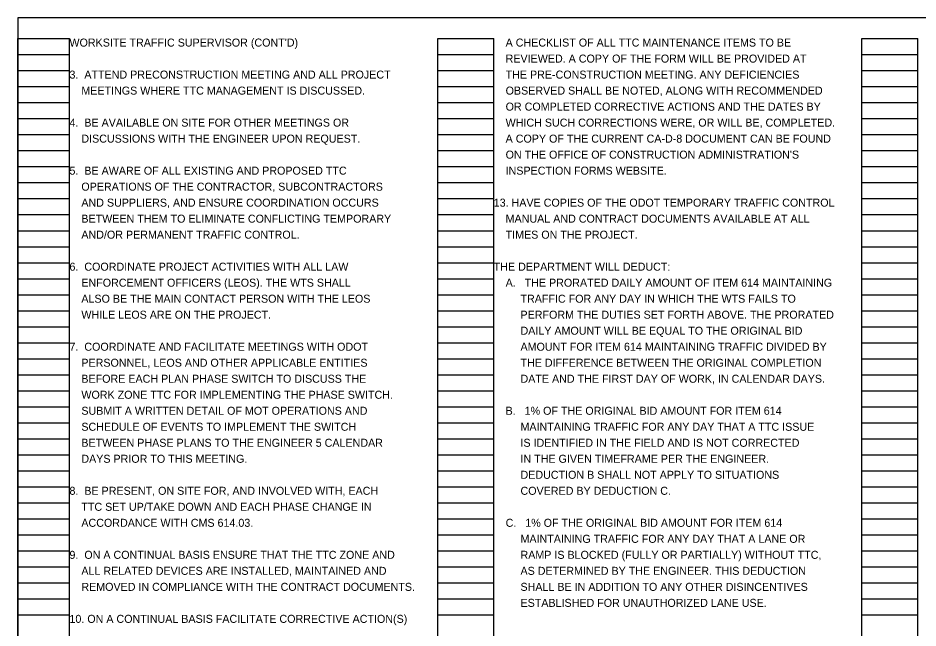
# Model space of a CAD drawing. Extents: x -34 to 2132911, y 0 to 658646.
# Drawn here: x 69.5 to 85.24, y 10.83 to 21.5 of the extents above; entities that cross this region are included whole.
import ezdxf

# ---------------------------------------------------------------- set-up
doc = ezdxf.new("R2010")
doc.units = 0
for name, color, linetype in [('SC_Scratch1', 7, 'Continuous'), ('SH_Data', 7, 'Continuous'), ('SH_Text', 7, 'Continuous')]:
    doc.layers.add(name, color=color, linetype=linetype)

msp = doc.modelspace()

# ---------------------------------------------------------------- linework, layer by layer
at = {"layer": 'SC_Scratch1'}
msp.add_lwpolyline([(69.5, 0.5), (100, 0.5), (100, 21.5), (69.5, 21.5)], close=True, dxfattribs=at)
at = {"layer": 'SH_Data'}
for p, q in [((69.5, 0.98), (69.5, 21.14)), ((69.5, 21.14), (70.4, 21.14)), ((70.4, 0.98), (70.4, 21.14)), ((76.84, 0.98), (76.84, 21.14)), ((76.84, 21.14), (77.82, 21.14)), ((77.82, 0.98), (77.82, 21.14)), ((84.26, 0.98), (84.26, 21.14)), ((84.26, 21.14), (85.24, 21.14)), ((85.24, 0.98), (85.24, 21.14)), ((69.5, 20.86), (70.4, 20.86)), ((76.84, 20.86), (77.82, 20.86)), ((84.26, 20.86), (85.24, 20.86)), ((69.5, 20.58), (70.4, 20.58)), ((76.84, 20.58), (77.82, 20.58)), ((84.26, 20.58), (85.24, 20.58)), ((69.5, 20.3), (70.4, 20.3)), ((76.84, 20.3), (77.82, 20.3)), ((84.26, 20.3), (85.24, 20.3)), ((69.5, 20.02), (70.4, 20.02)), ((76.84, 20.02), (77.82, 20.02)), ((84.26, 20.02), (85.24, 20.02)), ((69.5, 19.74), (70.4, 19.74)), ((76.84, 19.74), (77.82, 19.74)), ((84.26, 19.74), (85.24, 19.74)), ((69.5, 19.46), (70.4, 19.46)), ((76.84, 19.46), (77.82, 19.46)), ((84.26, 19.46), (85.24, 19.46)), ((69.5, 19.18), (70.4, 19.18)), ((76.84, 19.18), (77.82, 19.18)), ((84.26, 19.18), (85.24, 19.18)), ((69.5, 18.9), (70.4, 18.9)), ((76.84, 18.9), (77.82, 18.9)), ((84.26, 18.9), (85.24, 18.9)), ((69.5, 18.62), (70.4, 18.62)), ((76.84, 18.62), (77.82, 18.62)), ((84.26, 18.62), (85.24, 18.62)), ((69.5, 18.34), (70.4, 18.34)), ((76.84, 18.34), (77.82, 18.34)), ((84.26, 18.34), (85.24, 18.34)), ((69.5, 18.06), (70.4, 18.06)), ((76.84, 18.06), (77.82, 18.06)), ((84.26, 18.06), (85.24, 18.06)), ((69.5, 17.78), (70.4, 17.78)), ((76.84, 17.78), (77.82, 17.78)), ((84.26, 17.78), (85.24, 17.78)), ((69.5, 17.5), (70.4, 17.5)), ((76.84, 17.5), (77.82, 17.5)), ((84.26, 17.5), (85.24, 17.5)), ((69.5, 17.22), (70.4, 17.22)), ((76.84, 17.22), (77.82, 17.22)), ((84.26, 17.22), (85.24, 17.22)), ((69.5, 16.94), (70.4, 16.94)), ((76.84, 16.94), (77.82, 16.94)), ((84.26, 16.94), (85.24, 16.94)), ((69.5, 16.66), (70.4, 16.66)), ((76.84, 16.66), (77.82, 16.66)), ((84.26, 16.66), (85.24, 16.66)), ((69.5, 16.38), (70.4, 16.38)), ((76.84, 16.38), (77.82, 16.38)), ((84.26, 16.38), (85.24, 16.38)), ((69.5, 16.1), (70.4, 16.1)), ((76.84, 16.1), (77.82, 16.1)), ((84.26, 16.1), (85.24, 16.1)), ((69.5, 15.82), (70.4, 15.82)), ((76.84, 15.82), (77.82, 15.82)), ((84.26, 15.82), (85.24, 15.82)), ((69.5, 15.54), (70.4, 15.54)), ((76.84, 15.54), (77.82, 15.54)), ((84.26, 15.54), (85.24, 15.54)), ((69.5, 15.26), (70.4, 15.26)), ((76.84, 15.26), (77.82, 15.26)), ((84.26, 15.26), (85.24, 15.26)), ((69.5, 14.98), (70.4, 14.98)), ((76.84, 14.98), (77.82, 14.98)), ((84.26, 14.98), (85.24, 14.98)), ((69.5, 14.7), (70.4, 14.7)), ((76.84, 14.7), (77.82, 14.7)), ((84.26, 14.7), (85.24, 14.7)), ((69.5, 14.42), (70.4, 14.42)), ((76.84, 14.42), (77.82, 14.42)), ((84.26, 14.42), (85.24, 14.42)), ((69.5, 14.14), (70.4, 14.14)), ((76.84, 14.14), (77.82, 14.14)), ((84.26, 14.14), (85.24, 14.14)), ((69.5, 13.86), (70.4, 13.86)), ((76.84, 13.86), (77.82, 13.86)), ((84.26, 13.86), (85.24, 13.86)), ((69.5, 13.58), (70.4, 13.58)), ((76.84, 13.58), (77.82, 13.58)), ((84.26, 13.58), (85.24, 13.58)), ((69.5, 13.3), (70.4, 13.3)), ((76.84, 13.3), (77.82, 13.3)), ((84.26, 13.3), (85.24, 13.3)), ((69.5, 13.02), (70.4, 13.02)), ((76.84, 13.02), (77.82, 13.02)), ((84.26, 13.02), (85.24, 13.02)), ((69.5, 12.74), (70.4, 12.74)), ((76.84, 12.74), (77.82, 12.74)), ((84.26, 12.74), (85.24, 12.74)), ((69.5, 12.46), (70.4, 12.46)), ((76.84, 12.46), (77.82, 12.46)), ((84.26, 12.46), (85.24, 12.46)), ((69.5, 12.18), (70.4, 12.18)), ((76.84, 12.18), (77.82, 12.18)), ((84.26, 12.18), (85.24, 12.18)), ((69.5, 11.9), (70.4, 11.9)), ((76.84, 11.9), (77.82, 11.9)), ((84.26, 11.9), (85.24, 11.9)), ((69.5, 11.62), (70.4, 11.62)), ((76.84, 11.62), (77.82, 11.62)), ((84.26, 11.62), (85.24, 11.62)), ((69.5, 11.34), (70.4, 11.34)), ((76.84, 11.34), (77.82, 11.34)), ((84.26, 11.34), (85.24, 11.34)), ((69.5, 11.06), (70.4, 11.06)), ((76.84, 11.06), (77.82, 11.06)), ((84.26, 11.06), (85.24, 11.06))]:
    msp.add_line(p, q, dxfattribs=at)

# ---------------------------------------------------------------- texts
at = {"layer": 'SH_Text'}
for s, p in [("WORKSITE TRAFFIC SUPERVISOR (CONT'D)", (70.4, 21)), ('    A CHECKLIST OF ALL TTC MAINTENANCE ITEMS TO BE', (77.82, 21)), ('    REVIEWED. A COPY OF THE FORM WILL BE PROVIDED AT', (77.82, 20.72)), ('3.  ATTEND PRECONSTRUCTION MEETING AND ALL PROJECT', (70.4, 20.44)), ('    THE PRE-CONSTRUCTION MEETING. ANY DEFICIENCIES', (77.82, 20.44)), ('    MEETINGS WHERE TTC MANAGEMENT IS DISCUSSED.', (70.4, 20.16)), ('    OBSERVED SHALL BE NOTED, ALONG WITH RECOMMENDED', (77.82, 20.16)), ('    OR COMPLETED CORRECTIVE ACTIONS AND THE DATES BY', (77.82, 19.88)), ('4.  BE AVAILABLE ON SITE FOR OTHER MEETINGS OR', (70.4, 19.6)), ('    WHICH SUCH CORRECTIONS WERE, OR WILL BE, COMPLETED.', (77.82, 19.6)), ('    DISCUSSIONS WITH THE ENGINEER UPON REQUEST.', (70.4, 19.32)), ('    A COPY OF THE CURRENT CA-D-8 DOCUMENT CAN BE FOUND', (77.82, 19.32)), ("    ON THE OFFICE OF CONSTRUCTION ADMINISTRATION'S", (77.82, 19.04)), ('5.  BE AWARE OF ALL EXISTING AND PROPOSED TTC', (70.4, 18.76)), ('    INSPECTION FORMS WEBSITE.', (77.82, 18.76)), ('    OPERATIONS OF THE CONTRACTOR, SUBCONTRACTORS', (70.4, 18.48)), ('    AND SUPPLIERS, AND ENSURE COORDINATION OCCURS', (70.4, 18.2)), ('13. HAVE COPIES OF THE ODOT TEMPORARY TRAFFIC CONTROL', (77.82, 18.2)), ('    BETWEEN THEM TO ELIMINATE CONFLICTING TEMPORARY', (70.4, 17.92)), ('    MANUAL AND CONTRACT DOCUMENTS AVAILABLE AT ALL', (77.82, 17.92)), ('    AND/OR PERMANENT TRAFFIC CONTROL.', (70.4, 17.64)), ('    TIMES ON THE PROJECT.', (77.82, 17.64)), ('6.  COORDINATE PROJECT ACTIVITIES WITH ALL LAW', (70.4, 17.08)), ('THE DEPARTMENT WILL DEDUCT:', (77.82, 17.08)), ('    ENFORCEMENT OFFICERS (LEOS). THE WTS SHALL', (70.4, 16.8)), ('    A.   THE PRORATED DAILY AMOUNT OF ITEM 614 MAINTAINING', (77.82, 16.8)), ('    ALSO BE THE MAIN CONTACT PERSON WITH THE LEOS', (70.4, 16.52)), ('         TRAFFIC FOR ANY DAY IN WHICH THE WTS FAILS TO', (77.82, 16.52)), ('    WHILE LEOS ARE ON THE PROJECT.', (70.4, 16.24)), ('         PERFORM THE DUTIES SET FORTH ABOVE. THE PRORATED', (77.82, 16.24)), ('         DAILY AMOUNT WILL BE EQUAL TO THE ORIGINAL BID', (77.82, 15.96)), ('7.  COORDINATE AND FACILITATE MEETINGS WITH ODOT', (70.4, 15.68)), ('         AMOUNT FOR ITEM 614 MAINTAINING TRAFFIC DIVIDED BY', (77.82, 15.68)), ('    PERSONNEL, LEOS AND OTHER APPLICABLE ENTITIES', (70.4, 15.4)), ('         THE DIFFERENCE BETWEEN THE ORIGINAL COMPLETION', (77.82, 15.4)), ('    BEFORE EACH PLAN PHASE SWITCH TO DISCUSS THE', (70.4, 15.12)), ('         DATE AND THE FIRST DAY OF WORK, IN CALENDAR DAYS.', (77.82, 15.12)), ('    WORK ZONE TTC FOR IMPLEMENTING THE PHASE SWITCH.', (70.4, 14.84)), ('    SUBMIT A WRITTEN DETAIL OF MOT OPERATIONS AND', (70.4, 14.56)), ('    B.   1% OF THE ORIGINAL BID AMOUNT FOR ITEM 614', (77.82, 14.56)), ('    SCHEDULE OF EVENTS TO IMPLEMENT THE SWITCH', (70.4, 14.28)), ('         MAINTAINING TRAFFIC FOR ANY DAY THAT A TTC ISSUE', (77.82, 14.28)), ('    BETWEEN PHASE PLANS TO THE ENGINEER 5 CALENDAR', (70.4, 14)), ('         IS IDENTIFIED IN THE FIELD AND IS NOT CORRECTED', (77.82, 14)), ('    DAYS PRIOR TO THIS MEETING.', (70.4, 13.72)), ('         IN THE GIVEN TIMEFRAME PER THE ENGINEER.', (77.82, 13.72)), ('         DEDUCTION B SHALL NOT APPLY TO SITUATIONS', (77.82, 13.44)), ('8.  BE PRESENT, ON SITE FOR, AND INVOLVED WITH, EACH', (70.4, 13.16)), ('         COVERED BY DEDUCTION C.', (77.82, 13.16)), ('    TTC SET UP/TAKE DOWN AND EACH PHASE CHANGE IN', (70.4, 12.88)), ('    ACCORDANCE WITH CMS 614.03.', (70.4, 12.6)), ('    C.   1% OF THE ORIGINAL BID AMOUNT FOR ITEM 614', (77.82, 12.6)), ('         MAINTAINING TRAFFIC FOR ANY DAY THAT A LANE OR', (77.82, 12.32)), ('9.  ON A CONTINUAL BASIS ENSURE THAT THE TTC ZONE AND', (70.4, 12.04)), ('         RAMP IS BLOCKED (FULLY OR PARTIALLY) WITHOUT TTC,', (77.82, 12.04)), ('    ALL RELATED DEVICES ARE INSTALLED, MAINTAINED AND', (70.4, 11.76)), ('         AS DETERMINED BY THE ENGINEER. THIS DEDUCTION', (77.82, 11.76)), ('    REMOVED IN COMPLIANCE WITH THE CONTRACT DOCUMENTS.', (70.4, 11.48)), ('         SHALL BE IN ADDITION TO ANY OTHER DISINCENTIVES', (77.82, 11.48)), ('         ESTABLISHED FOR UNAUTHORIZED LANE USE.', (77.82, 11.2)), ('10. ON A CONTINUAL BASIS FACILITATE CORRECTIVE ACTION(S)', (70.4, 10.92))]:
    msp.add_text(s, height=0.14, dxfattribs=at).set_placement(p)

doc.saveas('drawing.dxf')
